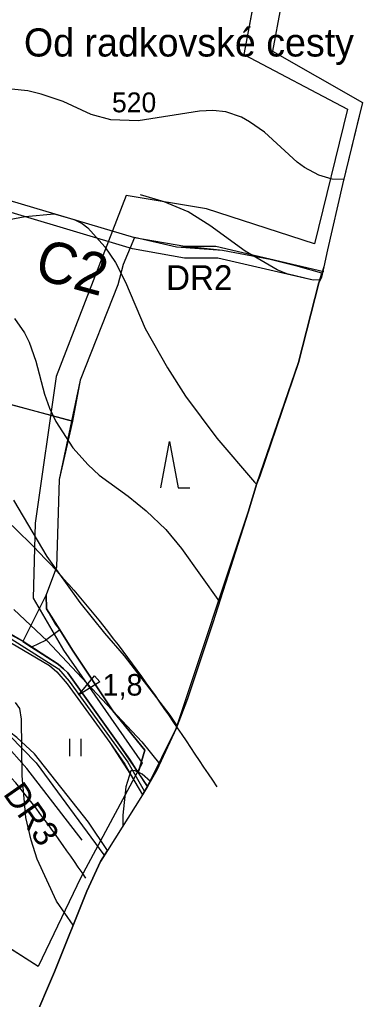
# Model space of a CAD drawing. Extents: x -684583 to -680383, y -1157874 to -1154904.
# Drawn here: x -682578 to -682371, y -1156305 to -1155713 of the extents above; entities that cross this region are included whole.
import ezdxf

# ---------------------------------------------------------------- set-up
doc = ezdxf.new("R2010")
doc.units = 0
for name, color, linetype in [('01_MÍSTNÍ_NÁZVY', 7, 'Continuous'), ('01_OBVOD PÚ', 7, 'Continuous'), ('01_SPRÁV_HRANICE', 7, 'Continuous'), ('01_VRSTEVNICE', 7, 'Continuous'), ('02_KULTURY NÁVRH', 7, 'Continuous'), ('02_KULTURY STAV', 7, 'Continuous'), ('03_PC_NÁVRH', 7, 'Continuous'), ('03_PC_OBJEKTY_NÁVRH', 7, 'Continuous'), ('03_PC_POPIS_NÁVRH', 7, 'Continuous'), ('05_VHO_MELIORACE', 7, 'Continuous'), ('05_VHO_V_TOK', 7, 'Continuous'), ('06_BIOGEOGRAFIE', 7, 'Continuous')]:
    doc.layers.add(name, color=color, linetype=linetype)

msp = doc.modelspace()

# ---------------------------------------------------------------- linework, layer by layer
at = {"layer": '01_OBVOD PÚ'}
msp.add_lwpolyline([(-682415.34, -1155677.48), (-682425.43, -1155731.81), (-682370.95, -1155762.69), (-682372.32, -1155768.33), (-682382.94, -1155812.42), (-682392.09, -1155851.75), (-682394.33, -1155862.14), (-682395.68, -1155868.37), (-682397.4, -1155871.72), (-682409.71, -1155920), (-682433.11, -1155988.6), (-682434.83, -1155993.05), (-682439.97, -1156010.43), (-682461.51, -1156077.19), (-682476.86, -1156123.27), (-682483.55, -1156141), (-682495.32, -1156166.31), (-682500.96, -1156176.19), (-682504.04, -1156181.13), (-682525.25, -1156214.91), (-682529.35, -1156221.47), (-682537.57, -1156239.43), (-682557.32, -1156288.22), (-682596.72, -1156380.07)], dxfattribs=at)
at = {"layer": '01_SPRÁV_HRANICE'}
msp.add_lwpolyline([(-682415.34, -1155677.48), (-682425.43, -1155731.81), (-682370.95, -1155762.69), (-682372.32, -1155768.33), (-682382.94, -1155812.42), (-682392.09, -1155851.75), (-682394.33, -1155862.14), (-682395.68, -1155868.37), (-682397.4, -1155871.72), (-682409.71, -1155920), (-682433.11, -1155988.6), (-682434.83, -1155993.05), (-682439.97, -1156010.43), (-682461.51, -1156077.19), (-682476.86, -1156123.27), (-682483.55, -1156141), (-682495.32, -1156166.31), (-682500.96, -1156176.19), (-682504.04, -1156181.13), (-682525.25, -1156214.91), (-682529.35, -1156221.47), (-682537.57, -1156239.43), (-682557.32, -1156288.22), (-682596.72, -1156380.07)], dxfattribs=at)
at = {"layer": '01_VRSTEVNICE'}
for points in [[(-682382.21, -1155809.3), (-682389.33, -1155809.04), (-682397.32, -1155806.76), (-682406.03, -1155802.05), (-682410.45, -1155798.77), (-682430.27, -1155780.8), (-682439.26, -1155774.38), (-682444.11, -1155771.67), (-682453.53, -1155768.39), (-682461.51, -1155767.53), (-682469.5, -1155768.1), (-682506.59, -1155773.81), (-682523.13, -1155773.24), (-682535.12, -1155769.96), (-682551.95, -1155762.25), (-682565.36, -1155757.69), (-682573.35, -1155755.83), (-682593.32, -1155753.7), (-682605.3, -1155750.7), (-682613.14, -1155745.85), (-682619.7, -1155739.43), (-682621.99, -1155735.01), (-682623.98, -1155726.45), (-682623.41, -1155691.93)], [(-682396.54, -1155870.05), (-682400.75, -1155870.09), (-682416.72, -1155866.38), (-682422.43, -1155863.96), (-682441.83, -1155852.55), (-682463.22, -1155837.14), (-682476.35, -1155828.87), (-682490.9, -1155822.88), (-682505.3, -1155818.6)], [(-682594.46, -1155835.29), (-682575.06, -1155831.72), (-682557.37, -1155830.15), (-682545.24, -1155833.43), (-682540.54, -1155835.86), (-682536.97, -1155838.57), (-682526.7, -1155849.98), (-682520.42, -1155859.39), (-682514.29, -1155871.38), (-682502.31, -1155899.34), (-682488.9, -1155923.16), (-682477.92, -1155940.27), (-682458.95, -1155965.66), (-682436.26, -1155992.2), (-682434.94, -1155993.43)], [(-682581.33, -1155893.34), (-682575.34, -1155901.9), (-682572.49, -1155907.61), (-682568.5, -1155919.02), (-682563.22, -1155938.99), (-682560.22, -1155947.55), (-682556.51, -1155955.54), (-682546.24, -1155971.51), (-682536.83, -1155981.78), (-682530.12, -1155988.06), (-682512.58, -1156000.75), (-682501.74, -1156009.46), (-682489.9, -1156020.87), (-682480.34, -1156032.28), (-682457.43, -1156064.56)], [(-682582.05, -1156003.18), (-682561.93, -1156037.13), (-682541.82, -1156064.95), (-682526.99, -1156083.49), (-682515, -1156097.18), (-682487.47, -1156132.99), (-682482.94, -1156139.68)], [(-682581.9, -1156069.22), (-682561.65, -1156088.05), (-682504.31, -1156149.25), (-682493.58, -1156162.57)], [(-682545.88, -1156259.96), (-682555.94, -1156245.39), (-682567.78, -1156220), (-682571.35, -1156208.59), (-682574.63, -1156194.89), (-682576.77, -1156169.79), (-682577.2, -1156135.55), (-682578.2, -1156128.99), (-682580.91, -1156125.43)], [(-682499.16, -1156173.04), (-682504.16, -1156168.65), (-682508.87, -1156166.51), (-682511.15, -1156166.65), (-682514.01, -1156176.35), (-682515.86, -1156193.47), (-682515.92, -1156200.04)]]:
    msp.add_lwpolyline(points, dxfattribs=at)
at = {"layer": '02_KULTURY NÁVRH'}
msp.add_lwpolyline([(-682562.23, -1156060.24), (-682576.31, -1156088.58), (-682571.24, -1156092.01), (-682554.97, -1156102.29), (-682551.87, -1156105.1), (-682549.23, -1156107.5), (-682522.01, -1156145.6), (-682506.53, -1156167.98), (-682502.54, -1156154.29), (-682522.03, -1156130.45), (-682546.27, -1156093.83), (-682554.09, -1156081.55), (-682562.06, -1156068.8)], close=True, dxfattribs=at)
at = {"layer": '02_KULTURY STAV'}
for points in [[(-682415.34, -1155677.48), (-682425.43, -1155731.81), (-682370.95, -1155762.69), (-682382.94, -1155812.42), (-682392.09, -1155851.75), (-682394.33, -1155862.14), (-682395.58, -1155865.96), (-682409.73, -1155861.86), (-682426.71, -1155857.66), (-682455.64, -1155852.31), (-682472.04, -1155850.36), (-682483.37, -1155850.15), (-682508.9, -1155844.44), (-682515.71, -1155860.72), (-682519, -1155873.01), (-682541.61, -1155930.68), (-682546.41, -1155955.28), (-682697.27, -1155915.21), (-682661.35, -1155805), (-682657.41, -1155794.38), (-682647.1, -1155761.89), (-682625.87, -1155693.99)], [(-682492.94, -1155995.63), (-682487.69, -1155967.63), (-682482.44, -1155995.63), (-682475.44, -1155995.63)], [(-682695.09, -1156023.72), (-682560.35, -1156103.1), (-682555.83, -1156106.79), (-682549.53, -1156114.2), (-682523.8, -1156149.51), (-682511.2, -1156168.84), (-682504.04, -1156181.13), (-682500.96, -1156176.19), (-682511.81, -1156159.62), (-682549.23, -1156107.5), (-682551.87, -1156105.1), (-682554.97, -1156102.29), (-682576.25, -1156088.48), (-682693.08, -1156020.51)], [(-682695.09, -1156023.72), (-682560.35, -1156103.1), (-682555.83, -1156106.79), (-682549.53, -1156114.2), (-682523.8, -1156149.51), (-682514.63, -1156162.56), (-682504.04, -1156181.13), (-682525.25, -1156214.91), (-682536.68, -1156197.77), (-682569.3, -1156156.35), (-682580.04, -1156146.44)], [(-682596.72, -1156380.07), (-682557.32, -1156288.22), (-682537.57, -1156239.43), (-682529.35, -1156221.47), (-682529.35, -1156221.47), (-682525.25, -1156214.91), (-682536.68, -1156197.77), (-682569.3, -1156156.35), (-682580.04, -1156146.44), (-682601.47, -1156130.49), (-682624.62, -1156116.74), (-682638.27, -1156107.54), (-682659.05, -1156095.72), (-682693.74, -1156078.06), (-682714.33, -1156069.98), (-682731.17, -1156065.1), (-682740.76, -1156063.41), (-682744.64, -1156063.3), (-682779.93, -1156155.81), (-682782.44, -1156169.94), (-682798.74, -1156209.36), (-682837.34, -1156293.13), (-682860.97, -1156340.11)], [(-682548.21, -1156147.37), (-682548.21, -1156157.87)], [(-682541.21, -1156147.37), (-682541.21, -1156157.87)]]:
    msp.add_lwpolyline(points, dxfattribs=at)
for points in [[(-682395.58, -1155865.96), (-682409.73, -1155861.86), (-682426.71, -1155857.66), (-682455.64, -1155852.31), (-682483.37, -1155850.15), (-682508.9, -1155844.44), (-682515.71, -1155860.72), (-682519, -1155873.01), (-682541.61, -1155930.68), (-682554.4, -1155990.65), (-682555.92, -1156043.51), (-682562.23, -1156060.24), (-682562.06, -1156068.8), (-682554.09, -1156081.55), (-682546.27, -1156093.83), (-682522.03, -1156130.45), (-682502.54, -1156154.29), (-682506.53, -1156167.98), (-682500.96, -1156176.19), (-682483.55, -1156141), (-682439.97, -1156010.43), (-682434.83, -1155993.05), (-682409.71, -1155920), (-682397.4, -1155871.72)], [(-682692.35, -1155915.71), (-682546.41, -1155955.28), (-682554.4, -1155990.65), (-682555.92, -1156043.51), (-682562.23, -1156060.24), (-682562.06, -1156068.8), (-682556.56, -1156078.19), (-682554.09, -1156081.55), (-682562.72, -1156088), (-682571.24, -1156092.01), (-682576.25, -1156088.48), (-682608.5, -1156071.15), (-682671.25, -1156034.36), (-682693.08, -1156020.51), (-682704.73, -1156012.95), (-682709.29, -1156011.25), (-682725.67, -1156001.43), (-682697.27, -1155915.21)], [(-682562.72, -1156088), (-682571.24, -1156092.01), (-682554.97, -1156102.29), (-682551.87, -1156105.1), (-682549.23, -1156107.5), (-682511.81, -1156159.62), (-682506.53, -1156167.98), (-682502.54, -1156154.29), (-682522.03, -1156130.45), (-682546.27, -1156093.83), (-682554.09, -1156081.55)]]:
    msp.add_lwpolyline(points, close=True, dxfattribs=at)
at = {"layer": '03_PC_NÁVRH'}
for points in [[(-682659.15, -1155799.78), (-682508.9, -1155844.44), (-682478.39, -1155849.54), (-682459.54, -1155849.54), (-682394.36, -1155864.99)], [(-682748.06, -1156060.15), (-682693.66, -1156080.3), (-682637.14, -1156111.72), (-682584.4, -1156145.39), (-682568.41, -1156161.75), (-682527.4, -1156217.35)]]:
    msp.add_lwpolyline(points, dxfattribs=at)
at = {"layer": '03_PC_OBJEKTY_NÁVRH'}
for points in [[(-682400.75, -1155870.09), (-682458.37, -1155856.77), (-682478.51, -1155856.77), (-682510.12, -1155851.15), (-682648.97, -1155809.69)], [(-682540.56, -1156208.64), (-682574.04, -1156165.3), (-682587.85, -1156149.61), (-682639.37, -1156116.57), (-682695.33, -1156085.89), (-682737, -1156069.49)]]:
    msp.add_lwpolyline(points, dxfattribs=at)
at = {"layer": '05_VHO_MELIORACE'}
for p, q in [((-682427.32, -1155652.04), (-682442.64, -1155733.79)), ((-682442.64, -1155733.79), (-682379.89, -1155766.86)), ((-682379.89, -1155766.86), (-682399.94, -1155848.22)), ((-682513.91, -1155819), (-682556.29, -1155928.43)), ((-682465.23, -1155827.02), (-682513.91, -1155819)), ((-682399.94, -1155848.22), (-682465.23, -1155827.02)), ((-682556.29, -1155928.43), (-682568.9, -1156017.02)), ((-682568.9, -1156017.02), (-682570.04, -1156062.28)), ((-682570.04, -1156062.28), (-682551.72, -1156093.79)), ((-682551.72, -1156093.79), (-682504.18, -1156161.97)), ((-682567.04, -1156285.02), (-682772.31, -1156153.49)), ((-682504.18, -1156161.97), (-682541.38, -1156231.07)), ((-682541.38, -1156231.07), (-682567.04, -1156285.02))]:
    msp.add_line(p, q, dxfattribs=at)
msp.add_lwpolyline([(-682427.32, -1155652.04), (-682442.64, -1155733.79), (-682379.89, -1155766.86), (-682399.94, -1155848.22), (-682465.23, -1155827.02), (-682513.91, -1155819), (-682556.29, -1155928.43), (-682568.9, -1156017.02), (-682570.04, -1156062.28), (-682551.72, -1156093.79), (-682504.18, -1156161.97), (-682541.38, -1156231.07), (-682567.04, -1156285.02), (-682772.31, -1156153.49), (-682747.8, -1156093.97), (-682704.39, -1155977.74), (-682664.8, -1155838.52), (-682635.04, -1155749.47), (-682580.41, -1155551.03)], dxfattribs=at)
at = {"layer": '05_VHO_V_TOK'}
msp.add_lwpolyline([(-682740.74, -1156048.05), (-682734.56, -1156048.85), (-682730.18, -1156046.18), (-682726.95, -1156041.18), (-682721.44, -1156024.25), (-682716.22, -1156017.49), (-682710.77, -1156013.63), (-682706.96, -1156014.25), (-682672.72, -1156035.1), (-682583.35, -1156086.9), (-682554.85, -1156105.08), (-682548.26, -1156112.47), (-682512.95, -1156161.54), (-682502.95, -1156178.81)], dxfattribs=at)
msp.add_lwpolyline([(-682533.1, -1156109.17), (-682529.8, -1156112.92), (-682542.7, -1156120.97)], close=True, dxfattribs=at)
at = {"layer": '06_BIOGEOGRAFIE'}
for points in [[(-682856.86, -1155847.34), (-682791.42, -1155830.12), (-682727.71, -1155694.04), (-682681.22, -1155649.25), (-682596.84, -1155571.74), (-682571.01, -1155502.84), (-682602.01, -1155421.88), (-682614.06, -1155356.43), (-682565.85, -1155299.59), (-682515.91, -1155292.7)], [(-682538.3, -1156231.46), (-682619.23, -1156136.72), (-682741.49, -1156072.99), (-682905.07, -1155940.36), (-683017, -1155857.68), (-683037.66, -1155826.67), (-683017, -1155811.17), (-682820.7, -1155868.01), (-682758.71, -1155893.85), (-682674.33, -1155943.8), (-682548.63, -1156054.04), (-682459.09, -1156176.34)]]:
    msp.add_spline(points, degree=3, dxfattribs=at)

# ---------------------------------------------------------------- texts
at = {"layer": '01_MÍSTNÍ_NÁZVY'}
msp.add_text('Od radkovské cesty', height=17, dxfattribs=at).set_placement((-682575.71, -1155734.99))
at = {"layer": '01_VRSTEVNICE'}
msp.add_text('520', height=12, dxfattribs=at).set_placement((-682522.46, -1155768.71))
at = {"layer": '03_PC_OBJEKTY_NÁVRH'}
msp.add_text('DR2', height=15, dxfattribs=at).set_placement((-682489.73, -1155876.12))
msp.add_text('DR3', height=15, rotation=304.99202, dxfattribs=at).set_placement((-682588.72, -1156180.62))
at = {"layer": '03_PC_POPIS_NÁVRH'}
msp.add_text('C2', height=25, rotation=344.87773, dxfattribs=at).set_placement((-682570.35, -1155868.77))
at = {"layer": '05_VHO_V_TOK'}
msp.add_text('1,8', height=13, dxfattribs=at).set_placement((-682528.17, -1156121.21))

doc.saveas('drawing.dxf')
